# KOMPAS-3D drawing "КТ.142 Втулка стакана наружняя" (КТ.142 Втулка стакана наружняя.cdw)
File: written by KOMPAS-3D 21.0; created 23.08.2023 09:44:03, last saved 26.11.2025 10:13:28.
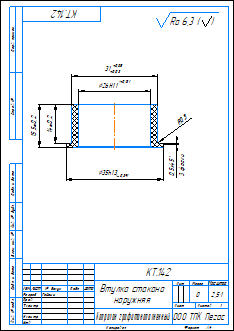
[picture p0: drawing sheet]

Sheet 1: A4, portrait

Document properties: Автор: Марсель; Организация: User; Полное имя файла: C:\Users\User\Desktop\Pelorus PRO доработки\ЗАФИКСИРОВАЛИ\Втулка стакана наружняя\КТ.142 Втулка стакана наружняя.cdw; Знак неуказанной шероховатости: 4; Параметр неуказанной шероховатости: Ra 6,3

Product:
- Part/product: КТ.142 Втулка стакана наружняя
    Комментарий: User

Title block, sheet 1: Наименование: Втулка стакана / наружняя; designation: КТ.142; Материал: Капролон графитонаполненный; Масса: 0; Количество листов документа: 1; organisation: ООО ТПК Пегас; Форматы листов документа: A4; stored path: C:\Marsel\KazanTarget\Ротатор\КТ.011 Втулка\КТ.011 Втулка.cdw; Разработал: Гайсин

Views: Вид 1, Местный разрез 1, Снизу
Referenced files in C:\Users\User\Desktop\Pelorus PRO доработки\ЗАФИКСИРОВАЛИ\Втулка стакана наружняя\: КТ.142 Втулка стакана наружняя.m3d, КТ.142 Втулка стакана наружняя_1.m3d
Referenced files in C:\Marsel\KazanTarget\KazanTarget3\ТП\КТ.011-01 Втулка\: КТ.011-01 Втулка.m3d
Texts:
  КТ.142 Втулка стакана наружняя
  Ra 6,3
  Ra 6,3 ( )
Dimensions and other numbers on the sheet: 26; 31; 35; 15,5±0,2; 14±0,2; 0,5; 3 фаски; 2,5:1; 1; 0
